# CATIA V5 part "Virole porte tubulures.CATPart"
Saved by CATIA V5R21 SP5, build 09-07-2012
Part number: Virole porte tubulures
Bounding box of the stored display mesh (mm): x -2422 to 2422, y -2422 to 2422, z 0 to 2395
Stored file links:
  \\etu.ad.univ-lorraine.fr\bordron1\Documents\Parts EPR\Virole porte tubulures.CATPart
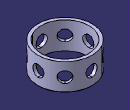
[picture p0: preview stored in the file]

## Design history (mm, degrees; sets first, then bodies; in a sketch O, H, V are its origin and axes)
AxisSystem1: origin (0, 0, 0), X (1, 0, 0), Y (0, 1, 0), Z (0, 0, 1)
Body1 (main body)
  Sketch1 on YZ plane of AxisSystem1, origin (0, 0, 0), H (0, 1, 0), V (0, 0, 1)
    line L1 (2140, 2395) -> (2140, 0)
    line L2 (2140, 2395) -> (2422, 2395)
    line L3 (2140, 0) -> (2372, 0)
    point P4 (2372, 0)
    point P5 (2372, 0)
    line L4 (2422, 2395) -> (2422, 50)
    point P6 (2422, 50)
    arc A1 centre (2422, 0) radius 50 from (2422, 50) to (2372, 0) ccw
    point P7 (2422, 0)
    point P8 (2422, 50)
    point P9 (2422, 50)
    reference intersected line E1 through (0, 0) direction (0, 1) from ZX plane of AxisSystem1
    reference projected line E2 through (0, 0) direction (1, 0) from edge [YZ plane of AxisSystem1 | XY plane of AxisSystem1]
    distance L1 E1 = 2140
    distance L2 L3 = 2395
    length L3 = 232
    radius A1 = 50
    vertical: L1 V, L4 V
    horizontal: L2 H, L3 H
    coincidence: P9 L4, P9 P6, L3 E2, P8 P6, P7 L4, P5 P4, P7 L3
  Shaft1: profile Sketch1, axis edge [ZX plane of AxisSystem1 | YZ plane of AxisSystem1], angle 360
  Fillet1: radius 10, on edge [face of Shaft1 from Sketch1.A1 | face of Shaft1 from Sketch1.L4]
  Sketch2 on ZX plane of AxisSystem1, origin (0, 0, 0), H (0, 0, 1), V (1, 0, 0)
    circle A1 centre (1197.5, 0) radius 500
    point P1 (1197.5, 0)
    projected line E1 (2395, 2140) -> (2395, -2140) from edge [face of Shaft1 from Sketch1.L2 | face of Shaft1 from Sketch1.L1]
    projected line E2 (0, 2140) -> (0, -2140) from edge [face of Shaft1 from Sketch1.L1 | face of Shaft1 from Sketch1.L3]
    reference projected line E3 through (0, 0) direction (1, 0) from edge [ZX plane of AxisSystem1 | YZ plane of AxisSystem1]
    radius A1 = 500
    equidistance: E2 E1 P1
    coincidence: P1 E3
  Pocket1: profile Sketch2, direction (0, -1, 0), through (limit type 3)
  CircPattern1: of Pocket1, instances 8, angular step 45, axis from edge [ZX plane of AxisSystem1 | YZ plane of AxisSystem1]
